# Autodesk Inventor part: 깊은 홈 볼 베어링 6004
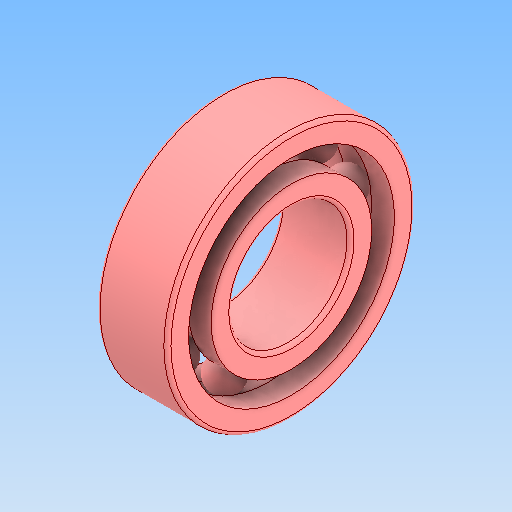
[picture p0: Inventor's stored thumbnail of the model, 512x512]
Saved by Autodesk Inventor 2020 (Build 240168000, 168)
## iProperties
Created: 2025-11
Part Number: 깊은 홈 볼 베어링 6004
Material: 강철, 연강
Description: 깊은 그루브 볼 베어링
Document SubType Name: Modeling
Designer: PC2-06
Density: 7.85 g/cm^3
Appearance: 기본값
Author: jhkim
Sending System: Autodesk Inventor 2026
Preprocessor: ST-DEVELOPER v20.1
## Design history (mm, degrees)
feature "Solid1"
feature "Solid1:1"
feature "Solid1:2"
feature "Solid1:3"
feature "Solid1:4"
feature "Solid1:5"
feature "Solid1:6"
feature "Solid1:7"
feature "Solid1:8"
feature "Solid1:9"
feature "Solid1:10"
node "솔리드1"
node "솔리드2"
node "솔리드3"
node "솔리드4"
node "솔리드5"
node "솔리드6"
node "솔리드7"
node "솔리드8"
node "솔리드9"
node "솔리드10"
node "솔리드11"
